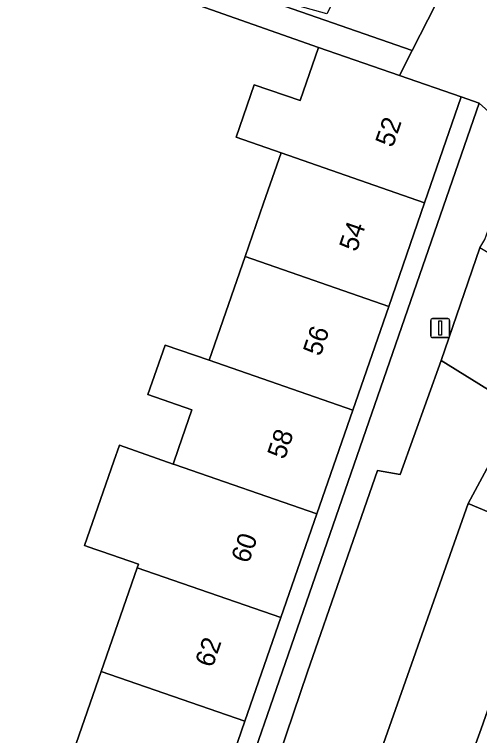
# Model space of a CAD drawing. Extents: x 160349 to 161355, y 381727 to 382854.
# Drawn here: x 160654.58 to 160678.99, y 382202.15 to 382240.01 of the extents above; entities that cross this region are included whole.
import ezdxf

# ---------------------------------------------------------------- set-up
doc = ezdxf.new("R2010")
doc.units = 0
for name, color, linetype in [('IMGEO_Erf', 7, 'Continuous'), ('IMGEO_Lichtmast', 7, 'Continuous'), ('IMGEO_Pand', 7, 'Continuous'), ('IMGEO_Pand_nummerreeks', 7, 'Continuous'), ('IMGEO_Parkeervlak_open', 7, 'Continuous'), ('IMGEO_Voetpad_open', 7, 'Continuous'), ('IMGEO_Woonerf_open', 7, 'Continuous')]:
    doc.layers.add(name, color=color, linetype=linetype)

msp = doc.modelspace()

# ---------------------------------------------------------------- linework, layer by layer
at = {"layer": 'IMGEO_Erf'}
for points in [[(160678.357, 382243.832), (160678.823, 382244.8), (160674.502, 382246.994), (160670.969, 382240.037), (160668.067, 382240.875), (160667.947, 382240.726), (160675.465, 382238.124)], [(160678.979, 382235.356), (160678.036, 382235.688), (160676.111, 382230.13), (160674.225, 382224.686), (160672.339, 382219.241), (160670.454, 382213.797), (160668.568, 382208.352), (160666.682, 382202.907), (160664.796, 382197.463), (160662.911, 382192.019), (160661.024, 382186.573), (160659.139, 382181.129), (160657.253, 382175.684), (160655.328, 382170.127), (160656.273, 382169.8)]]:
    msp.add_lwpolyline(points, close=True, dxfattribs=at)
msp.add_lwpolyline([(160657.25, 382200.081), (160659.136, 382205.525), (160661.021, 382210.969), (160661.085, 382211.153), (160659.168, 382211.817), (160658.805, 382211.943), (160658.262, 382212.131), (160659.802, 382216.569), (160660.088, 382217.393), (160662.916, 382216.412), (160663.2, 382217.232), (160663.9, 382219.251), (160661.585, 382220.055), (160662.488, 382222.659), (160664.802, 382221.856), (160666.688, 382227.301), (160667.661, 382230.11), (160668.574, 382232.745), (160666.212, 382233.565), (160667.168, 382236.324), (160669.579, 382235.489), (160670.547, 382238.283), (160657.113, 382243.023)], dxfattribs=at)
at = {"layer": 'IMGEO_Lichtmast'}
for p, q in [((160676.432, 382223.146), (160676.432, 382223.946)), ((160676.432, 382223.946), (160676.432, 382223.146)), ((160676.532, 382224.046), (160677.322, 382224.046)), ((160677.322, 382224.046), (160676.532, 382224.046)), ((160677.422, 382223.946), (160677.422, 382223.146)), ((160677.422, 382223.146), (160677.422, 382223.946)), ((160677.322, 382223.046), (160676.532, 382223.046)), ((160676.532, 382223.046), (160677.322, 382223.046))]:
    msp.add_line(p, q, dxfattribs=at)
msp.add_lwpolyline([(160676.852, 382223.921), (160677.002, 382223.921), (160677.002, 382223.171), (160676.852, 382223.171), (160676.852, 382223.921)], dxfattribs=at)
for centre, start, end in [((160676.532, 382223.946), 90, 180), ((160676.532, 382223.946), 90, 180), ((160677.322, 382223.946), 0, 90), ((160677.322, 382223.946), 360, 90), ((160676.532, 382223.146), 180, 270), ((160676.532, 382223.146), 180, 270), ((160677.322, 382223.146), 270, 0), ((160677.322, 382223.146), 270, 0)]:
    msp.add_arc(centre, 0.1, start, end, dxfattribs=at)
at = {"layer": 'IMGEO_Pand'}
for points in [[(160678.036, 382235.688), (160674.799, 382236.81), (160670.547, 382238.283), (160669.579, 382235.489), (160667.168, 382236.324), (160666.212, 382233.565), (160668.574, 382232.745), (160676.111, 382230.13)], [(160676.111, 382230.13), (160668.574, 382232.745), (160667.661, 382230.11), (160666.688, 382227.301), (160674.225, 382224.686)], [(160672.339, 382219.241), (160674.225, 382224.686), (160666.688, 382227.301), (160664.802, 382221.856)], [(160672.339, 382219.241), (160664.802, 382221.856), (160662.488, 382222.659), (160661.585, 382220.055), (160663.9, 382219.251), (160663.2, 382217.232), (160662.916, 382216.412), (160662.985, 382216.388), (160670.454, 382213.797)], [(160670.454, 382213.797), (160662.985, 382216.388), (160662.916, 382216.412), (160660.088, 382217.393), (160659.802, 382216.569), (160658.262, 382212.131), (160658.805, 382211.943), (160659.168, 382211.817), (160661.085, 382211.153), (160661.021, 382210.969), (160668.568, 382208.352)], [(160661.021, 382210.969), (160659.136, 382205.525), (160666.682, 382202.907), (160668.568, 382208.352)], [(160659.136, 382205.525), (160657.25, 382200.081), (160664.796, 382197.463), (160666.682, 382202.907)]]:
    msp.add_lwpolyline(points, close=True, dxfattribs=at)
at = {"layer": 'IMGEO_Parkeervlak_open'}
msp.add_lwpolyline([(160672.887, 382198.717), (160677.16, 382197.218), (160679.072, 382202.502), (160682.616, 382212.575), (160678.398, 382214.339)], close=True, dxfattribs=at)
at = {"layer": 'IMGEO_Voetpad_open'}
for points in [[(160711.752, 382219.855), (160707.84, 382222.072), (160704.228, 382224.198), (160707.001, 382229.593), (160702.34, 382231.516), (160699.942, 382232.777), (160699.802, 382232.502), (160683.087, 382240.991), (160683.264, 382241.34), (160678.357, 382243.832), (160675.465, 382238.124), (160674.799, 382236.81), (160678.036, 382235.688), (160678.979, 382235.356), (160682.3, 382232.389), (160684.352, 382231.328)], [(160657.113, 382243.023), (160670.547, 382238.283), (160674.799, 382236.81), (160675.465, 382238.124), (160667.947, 382240.726)], [(160682.3, 382232.389), (160678.979, 382235.356), (160656.273, 382169.8), (160655.119, 382166.468), (160634.794, 382107.787), (160639.616, 382106.019), (160640.607, 382108.902), (160638.62, 382111.527), (160640.555, 382116.871), (160639.534, 382117.379), (160643.391, 382128.676)], [(160668.101, 382200.032), (160669.967, 382205.508), (160673.64, 382216.076), (160674.829, 382215.869), (160676.985, 382221.847), (160679.01, 382227.764), (160679.264, 382228.194), (160680.577, 382231.881)]]:
    msp.add_lwpolyline(points, dxfattribs=at)
at = {"layer": 'IMGEO_Woonerf_open'}
msp.add_lwpolyline([(160684.833, 382224.862), (160684.525, 382225.041), (160684.262, 382224.616), (160679.01, 382227.764), (160676.985, 382221.847), (160681.078, 382219.315), (160678.398, 382214.339), (160682.616, 382212.575), (160679.072, 382202.502), (160677.16, 382197.218)], dxfattribs=at)
msp.add_lwpolyline([(160678.398, 382214.339), (160681.078, 382219.315), (160676.985, 382221.847), (160674.829, 382215.869), (160673.64, 382216.076), (160669.967, 382205.508), (160668.101, 382200.032), (160669.486, 382199.728), (160672.887, 382198.717)], close=True, dxfattribs=at)

# ---------------------------------------------------------------- texts
at = {"layer": 'IMGEO_Pand_nummerreeks'}
for s, rotation, p in [('52', 70.8978, (160674.434, 382232.989)), ('54', 70.8978, (160672.536, 382227.509)), ('56', 70.8957, (160670.638, 382222.026)), ('58', 70.8978, (160668.763, 382216.613)), ('60', 70.8978, (160666.87, 382211.15)), ('62', 70.8957, (160664.976, 382205.68))]:
    msp.add_text(s, height=1, rotation=rotation, dxfattribs=at).set_placement(p)

doc.saveas('drawing.dxf')
